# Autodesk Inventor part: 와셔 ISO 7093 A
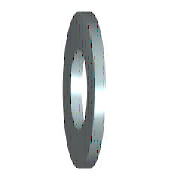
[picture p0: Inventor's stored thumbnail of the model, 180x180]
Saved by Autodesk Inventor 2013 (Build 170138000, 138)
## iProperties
Created: 2012-02
Part Number: 와셔 ISO 7093 A
Material: 스테인리스강
Description: 평면 와셔 - 대형 시리즈 - 제품 등급 A
Document SubType Name: Modeling
Standard: ISO 7093 A
Designer: mduedu
Standard Revision: First Edition 2000-06-01
Standards Organization: ISO
Language: ko-KR
Size Designation: ST 4 - 140 HV - A
Categories: <MemberInstance><Categories><Category DisplayName="조임쇠" InternalName="e4da775c-781d-43d5-af7c-5136215cf5a6" Mnemonic="FSTN"><Category DisplayName="와셔" InternalN
Density: 8.08 g/cm^3
IsCustomPart: 1
Author: mduedu
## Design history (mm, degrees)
sketch "스케치"
  geometry: C1 r 6 at (0, 0); C2 r 2.15 at (0, 0); 1 further point
  constraints: 2 centre point, 2 coincident
  dimensions: "d0" = 4.3 diameter of C2 (= SD1); "d1" = 12 diameter of C1 (= SD2)
extrude "본체" new body sketch "스케치" distance "d2" = 1 (= SD); taper "d3" = 0 deg
workaxis "Work Axis1"
workplane "Work Plane1"
body "Solid1"
other parameters: "SD1" = 4.3 [user parameter; used in 1 equation term], "SD2" = 12 [user parameter; used in 1 equation term], "SD" = 1 [user parameter; used in 1 equation term], "d4" = 0, "d5" = 0, "d6" = 0, "d7" = 0, "NND" = 4 [user parameter]
